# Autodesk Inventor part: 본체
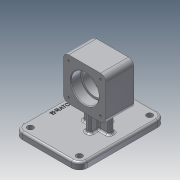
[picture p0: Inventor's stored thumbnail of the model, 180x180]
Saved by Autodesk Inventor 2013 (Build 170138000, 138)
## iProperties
Created: 2020-11
Part Number: 본체
Material: 알루미늄 6061
Document SubType Name: Modeling
Designer: user
Density: 2.71 g/cm^3
Mass: 685.719 g
Surface Area: 548.419 cm^2
Volume: 253.033 cm^3
Author: user
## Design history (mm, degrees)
sketch "스케치1"
  geometry: L1 (-32, -32)-(32, -32); L2 (32, -32)-(32, 32); L3 (32, 32)-(-32, 32); L4 (-32, 32)-(-32, -32); L5 (-32, -32)-(32, 32); L6 (32, -32)-(-32, 32); 1 further point
  constraints: 12 end point, 2 midpoint, 2 parallel, 1 horizontal, 1 perpendicular
  dimensions: "d0" = 64 distance of L3.end L2.end; "d1" = 64 distance of L2.end L1.end
extrude "돌출1" new body sketch "스케치1" stored distance "d2" = 42; taper "d3" = 0 deg
sketch "스케치2"
  geometry: L1 (32, -21)-(-32, -21) reference; L2 (-32, -21)-(-32, 21) reference; L3 (-32, 21)-(32, 21) reference; L4 (32, 21)-(32, -21) reference; L5 (0, 21)-(0, -21); L6 (0, 21)-(21, 21); L7 (21, 21)-(21, 6); L8 (21, 6)-(18, 6); L9 (18, 6)-(18, -6); L10 (18, -6)-(21, -6); L11 (21, -6)-(21, -21); L12 (21, -21)-(0, -21); 1 further point
  constraints: 16 end point, 4 perpendicular, 2 midpoint, 2 point on line, 1 collinear, 1 parallel
  dimensions: "d4" = 15 distance between parallel lines of L8 L6; "d6" = 15 distance between parallel lines of L1 L10; "d7" = 36 diameter of L9 L5; "d8" = 42 diameter of L11 L5; "d9" = 42 diameter of L7 L5
revolve "회전1" sketch "스케치2" stored, may be unused: angle "d10" = 90 deg
sketch "스케치3"
  geometry: A1 r 8 centre (24, -24) between (24, -32) and (32, -24) reference; A2 r 8 centre (24, 24) between (32, 24) and (24, 32) reference; A3 r 8 centre (-24, 24) between (-24, 32) and (-32, 24) reference; A4 r 8 centre (-24, -24) between (-32, -24) and (-24, -32) reference; 4 further points
  constraints: 4 coincident
hole "구멍1" sketch "스케치3" at (-24, 24), (24, 24), (24, -24), (-24, -24) diameter "d12" = 3.242; stored, may be unused: countersink angle "d16" = 90 deg, drill point angle "d18" = 118 deg; dims "d13" = 8, "d14" = 4, "d15" = 2, "d17" = 10
node "작업 평면1"
sketch "스케치8"
  geometry: L1 (-32, -21)-(-32, 21) reference; L2 (32, -21)-(32, 21) reference; L3 (62, 65)-(-36, 65); L4 (-36, 65)-(-36, -65); L5 (-36, -65)-(62, -65); L6 (62, -65)-(62, 65); 2 further points
  constraints: 8 end point, 2 parallel, 1 horizontal, 1 horizontal alignment, 1 midpoint, 1 perpendicular
  dimensions: "d38" = 98 distance of L5.end L4.end; "d39" = 130 distance of L4.end L3.end; "d40" = 36 distance from line of L4 point (0, 0)
extrude "돌출5" join sketch "스케치8" distance "d41" = 10; taper "d42" = 0 deg
sketch "스케치9"
  geometry: L1 (-62, 65)-(-62, -65) reference; L2 (-20, -4)-(20, -4); L3 (20, -4)-(20, 4); L4 (20, 4)-(-20, 4); L5 (-20, 4)-(-20, -4); L6 (0, -4)-(0, 4); L7 (-62, 65)-(-62, -65) reference; L8 (-4, -17)-(4, -17); L9 (4, -17)-(4, 17); L10 (4, 17)-(-4, 17); L11 (-4, 17)-(-4, -17); L12 (0, -17)-(0, 17); L13 (-4, 0)-(4, 0); 3 further points
  constraints: 22 end point, 8 midpoint, 4 parallel, 3 perpendicular, 2 horizontal, 2 horizontal alignment
  dimensions: "d43" = 40 distance of L4.end L3.end; "d44" = 8 distance of L3.end L2.end; "d45" = 62 distance between parallel lines of L6 L1; "d48" = 8 distance of L10.end L9.end; "d49" = 34 distance of L9.end L8.end; "d50" = 62 distance between parallel lines of L12 L1
extrude "돌출6" join sketch "스케치9" stored distance "d51" = 0; taper "d52" = 0 deg
fillet "모깎기2" dims "d53" = 8
fillet "모깎기3" dims "d54" = 12
sketch "스케치10"
  geometry: C1 r 4.5 at (-50, -53); C2 r 4.5 at (-50, 53); C3 r 4.5 at (24, 53); C4 r 4.5 at (24, -53); A1 r 12 centre (24, -53) between (24, -65) and (36, -53) reference; A2 r 12 centre (24, 53) between (36, 53) and (24, 65) reference; A3 r 12 centre (-50, 53) between (-50, 65) and (-62, 53) reference; A4 r 12 centre (-50, -53) between (-62, -53) and (-50, -65) reference; 1 further point
  constraints: 4 centre point, 4 coincident
  dimensions: "d55" = 9 diameter of C1; "d56" = 9 diameter of C2; "d57" = 9 diameter of C3; "d58" = 9 diameter of C4
extrude "돌출7" cut sketch "스케치10" stored distance "d59" = 9 (= d55); taper "d60" = 0 deg
sketch "스케치11"
  geometry: L1 (24, 65)-(-50, 65) reference; L2 (-62, 53)-(-62, -53) reference; 2 further points
  constraints: 1 other
  dimensions: "d61" = 65 distance from line of point (-52, 0) L1; "d62" = 10 distance from line of point (-52, 0) L2
feature "엠보싱1" sketch "스케치11" dims "d63" = 0.5, "d64" = 0
fillet "모깎기4" dims "d65" = 0.3
chamfer "모따기1" distance "d66" = 1; stored, may be unused: second distance "d67" = 2, angle "d68" = 45 deg
fillet "모깎기5" dims "d69" = 3
fillet "모깎기6" dims "d70" = 3
fillet "모깎기7" dims "d71" = 3
node "솔리드1"
mirror "대칭1"
node "절단 모서리 투영1"
